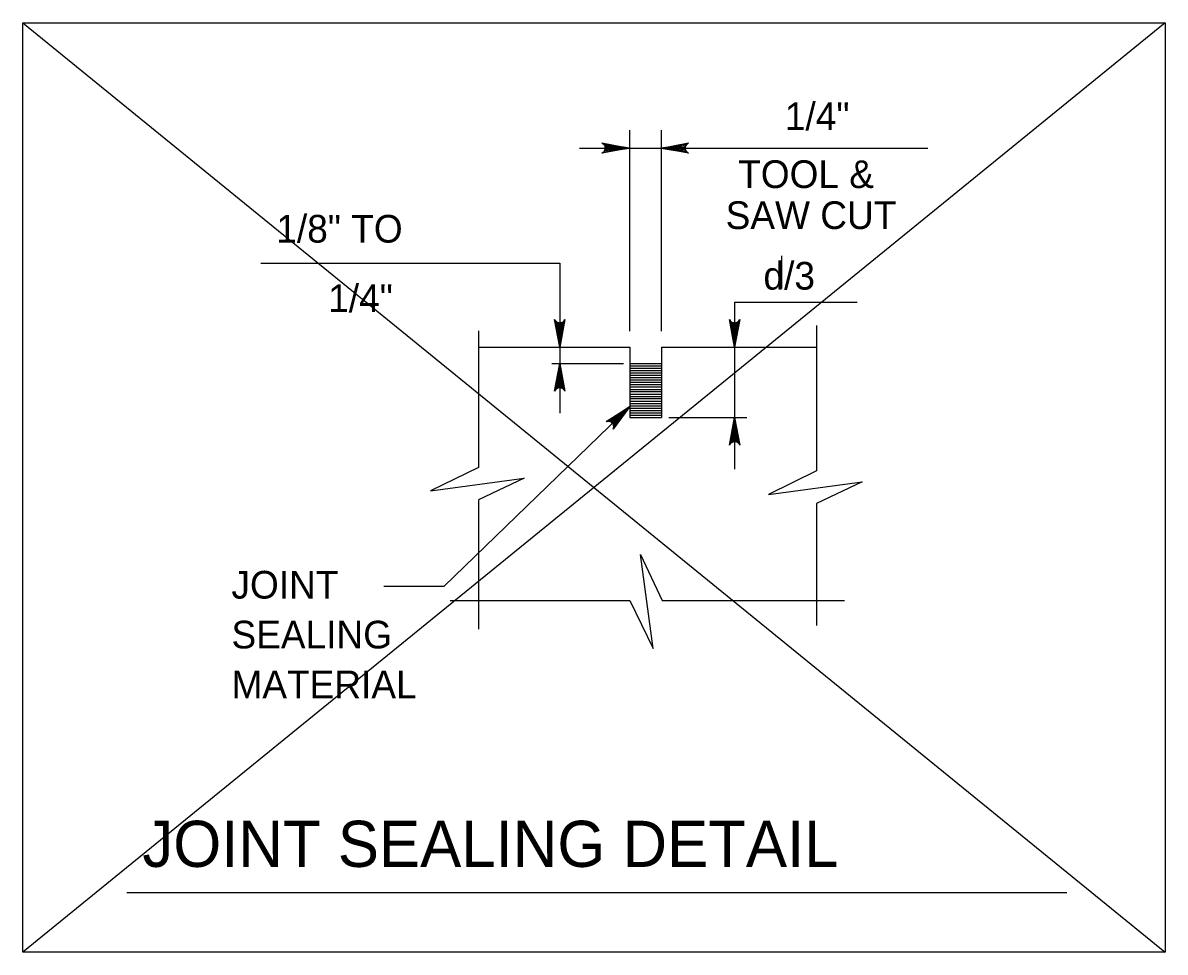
# Model space of a CAD drawing. Extents: x 638079 to 640019, y 297691 to 298879.
# Drawn here: x 638078.5 to 638202.3, y 298460 to 298560.7 of the extents above; entities that cross this region are included whole.
import ezdxf

# ---------------------------------------------------------------- set-up
doc = ezdxf.new("R2010")
doc.units = 0
for name, color, linetype in [('1', 7, 'Continuous'), ('2', 7, 'Continuous'), ('Level 1', 7, 'Continuous')]:
    doc.layers.add(name, color=color, linetype=linetype)

msp = doc.modelspace()

# ---------------------------------------------------------------- linework, layer by layer
at = {"layer": '1'}
for p, q in [((638144.26, 298549.04), (638144.26, 298527.26)), ((638147.69, 298549.04), (638147.69, 298527.26)), ((638138.83, 298547.09), (638176.59, 298547.09)), ((638104.31, 298534.63), (638136.71, 298534.63)), ((638136.71, 298534.63), (638136.71, 298518.38)), ((638160.77, 298531.89), (638160.77, 298535.44)), ((638155.65, 298530.4), (638155.65, 298512.31)), ((638155.65, 298530.4), (638168.92, 298530.4)), ((638127.89, 298527.31), (638127.89, 298512.51)), ((638164.52, 298527.89), (638164.52, 298512.13)), ((638127.89, 298525.54), (638144.31, 298525.54)), ((638144.31, 298525.54), (638144.31, 298517.93)), ((638147.74, 298525.54), (638147.74, 298517.93)), ((638147.74, 298525.54), (638164.52, 298525.54)), ((638135.84, 298523.76), (638143.6, 298523.76)), ((638144.31, 298523.76), (638147.74, 298523.76)), ((638144.31, 298523.51), (638147.74, 298523.51)), ((638144.31, 298523.26), (638147.74, 298523.26)), ((638144.31, 298523), (638147.74, 298523)), ((638144.31, 298522.75), (638147.74, 298522.75)), ((638144.31, 298522.49), (638147.74, 298522.49)), ((638144.31, 298522.24), (638147.74, 298522.24)), ((638144.31, 298521.99), (638147.74, 298521.99)), ((638144.31, 298521.73), (638147.74, 298521.73)), ((638144.31, 298521.48), (638147.74, 298521.48)), ((638144.31, 298521.23), (638147.74, 298521.23)), ((638144.31, 298520.97), (638147.74, 298520.97)), ((638144.31, 298520.72), (638147.74, 298520.72)), ((638144.31, 298520.46), (638147.74, 298520.46)), ((638144.31, 298520.21), (638147.74, 298520.21)), ((638144.31, 298519.96), (638147.74, 298519.96)), ((638144.31, 298519.7), (638147.74, 298519.7)), ((638124.17, 298499.65), (638144.31, 298519.1)), ((638144.31, 298519.45), (638147.74, 298519.45)), ((638144.31, 298519.2), (638147.74, 298519.2)), ((638144.31, 298518.94), (638147.74, 298518.94)), ((638144.31, 298518.69), (638147.74, 298518.69)), ((638144.31, 298518.43), (638147.74, 298518.43)), ((638144.31, 298518.18), (638147.74, 298518.18)), ((638144.31, 298517.93), (638147.74, 298517.93)), ((638148.52, 298517.93), (638156.99, 298517.93)), ((638127.89, 298509), (638127.89, 298495.01)), ((638164.52, 298508.61), (638164.52, 298495.4)), ((638117.64, 298499.65), (638124.17, 298499.65)), ((638124.84, 298498.11), (638144.3, 298498.11)), ((638147.82, 298498.11), (638167.56, 298498.11))]:
    msp.add_line(p, q, dxfattribs=at)
for points in [[(638144.26, 298547.09), (638141.28, 298546.53), (638141.39, 298546.61), (638141.51, 298546.69), (638141.57, 298546.79), (638141.63, 298546.89), (638141.64, 298546.99), (638141.66, 298547.09), (638141.64, 298547.19), (638141.63, 298547.29), (638141.57, 298547.39), (638141.51, 298547.49), (638141.39, 298547.57), (638141.28, 298547.65), (638144.26, 298547.09), (638141.39, 298547.57), (638141.51, 298547.49), (638144.26, 298547.09), (638141.57, 298547.39), (638141.63, 298547.29), (638144.26, 298547.09), (638141.64, 298547.19), (638141.66, 298547.09), (638144.26, 298547.09), (638141.64, 298546.99), (638141.63, 298546.89), (638144.26, 298547.09), (638141.57, 298546.79), (638141.51, 298546.69), (638144.26, 298547.09), (638141.39, 298546.61)], [(638147.69, 298547.09), (638150.67, 298547.65), (638150.56, 298547.57), (638150.44, 298547.49), (638150.38, 298547.39), (638150.32, 298547.29), (638150.31, 298547.19), (638150.29, 298547.09), (638150.31, 298546.99), (638150.32, 298546.89), (638150.38, 298546.79), (638150.44, 298546.69), (638150.56, 298546.61), (638150.67, 298546.53), (638147.69, 298547.09), (638150.56, 298546.61), (638150.44, 298546.69), (638147.69, 298547.09), (638150.38, 298546.79), (638150.32, 298546.89), (638147.69, 298547.09), (638150.31, 298546.99), (638150.29, 298547.09), (638147.69, 298547.09), (638150.31, 298547.19), (638150.32, 298547.29), (638147.69, 298547.09), (638150.38, 298547.39), (638150.44, 298547.49), (638147.69, 298547.09), (638150.56, 298547.57)], [(638136.71, 298525.54), (638136.15, 298528.52), (638136.23, 298528.41), (638136.31, 298528.29), (638136.41, 298528.23), (638136.51, 298528.17), (638136.61, 298528.16), (638136.71, 298528.14), (638136.81, 298528.16), (638136.91, 298528.17), (638137.01, 298528.23), (638137.11, 298528.29), (638137.18, 298528.41), (638137.26, 298528.52), (638136.71, 298525.54), (638137.18, 298528.41), (638137.11, 298528.29), (638136.71, 298525.54), (638137.01, 298528.23), (638136.91, 298528.17), (638136.71, 298525.54), (638136.81, 298528.16), (638136.71, 298528.14), (638136.71, 298525.54), (638136.61, 298528.16), (638136.51, 298528.17), (638136.71, 298525.54), (638136.41, 298528.23), (638136.31, 298528.29), (638136.71, 298525.54), (638136.23, 298528.41)], [(638155.65, 298525.54), (638155.09, 298528.52), (638155.17, 298528.41), (638155.25, 298528.29), (638155.35, 298528.23), (638155.45, 298528.17), (638155.55, 298528.16), (638155.65, 298528.14), (638155.75, 298528.16), (638155.85, 298528.17), (638155.95, 298528.23), (638156.05, 298528.29), (638156.13, 298528.41), (638156.21, 298528.52), (638155.65, 298525.54), (638156.13, 298528.41), (638156.05, 298528.29), (638155.65, 298525.54), (638155.95, 298528.23), (638155.85, 298528.17), (638155.65, 298525.54), (638155.75, 298528.16), (638155.65, 298528.14), (638155.65, 298525.54), (638155.55, 298528.16), (638155.45, 298528.17), (638155.65, 298525.54), (638155.35, 298528.23), (638155.25, 298528.29), (638155.65, 298525.54), (638155.17, 298528.41)], [(638136.71, 298523.76), (638137.26, 298520.78), (638137.18, 298520.9), (638137.11, 298521.01), (638137.01, 298521.07), (638136.91, 298521.13), (638136.81, 298521.15), (638136.71, 298521.16), (638136.61, 298521.15), (638136.51, 298521.13), (638136.41, 298521.07), (638136.31, 298521.01), (638136.23, 298520.9), (638136.15, 298520.78), (638136.71, 298523.76), (638136.23, 298520.9), (638136.31, 298521.01), (638136.71, 298523.76), (638136.41, 298521.07), (638136.51, 298521.13), (638136.71, 298523.76), (638136.61, 298521.15), (638136.71, 298521.16), (638136.71, 298523.76), (638136.81, 298521.15), (638136.91, 298521.13), (638136.71, 298523.76), (638137.01, 298521.07), (638137.11, 298521.01), (638136.71, 298523.76), (638137.18, 298520.9)], [(638144.31, 298519.1), (638142.51, 298516.66), (638142.54, 298516.79), (638142.57, 298516.93), (638142.54, 298517.04), (638142.52, 298517.16), (638142.46, 298517.24), (638142.41, 298517.33), (638142.33, 298517.39), (638142.25, 298517.45), (638142.13, 298517.48), (638142.02, 298517.52), (638141.88, 298517.5), (638141.75, 298517.48), (638144.31, 298519.1), (638141.88, 298517.5), (638142.02, 298517.52), (638144.31, 298519.1), (638142.13, 298517.48), (638142.25, 298517.45), (638144.31, 298519.1), (638142.33, 298517.39), (638142.41, 298517.33), (638144.31, 298519.1), (638142.46, 298517.24), (638142.52, 298517.16), (638144.31, 298519.1), (638142.54, 298517.04), (638142.57, 298516.93), (638144.31, 298519.1), (638142.54, 298516.79)], [(638155.65, 298517.93), (638156.21, 298514.94), (638156.13, 298515.06), (638156.05, 298515.17), (638155.95, 298515.23), (638155.85, 298515.29), (638155.75, 298515.31), (638155.65, 298515.33), (638155.55, 298515.31), (638155.45, 298515.29), (638155.35, 298515.23), (638155.25, 298515.17), (638155.17, 298515.06), (638155.09, 298514.94), (638155.65, 298517.93), (638155.17, 298515.06), (638155.25, 298515.17), (638155.65, 298517.93), (638155.35, 298515.23), (638155.45, 298515.29), (638155.65, 298517.93), (638155.55, 298515.31), (638155.65, 298515.33), (638155.65, 298517.93), (638155.75, 298515.31), (638155.85, 298515.29), (638155.65, 298517.93), (638155.95, 298515.23), (638156.05, 298515.17), (638155.65, 298517.93), (638156.13, 298515.06)], [(638127.89, 298512.51), (638122.71, 298509.98), (638132.85, 298511.36), (638127.89, 298509)], [(638164.52, 298512.13), (638159.34, 298509.59), (638169.49, 298510.97), (638164.52, 298508.61)], [(638144.3, 298498.11), (638146.84, 298492.92), (638145.46, 298503.07), (638147.82, 298498.11)]]:
    msp.add_lwpolyline(points, dxfattribs=at)
at = {"layer": '2'}
for p, q in [((638078.54, 298560.66), (638202.3, 298460.02)), ((638202.3, 298560.66), (638078.54, 298460.02))]:
    msp.add_line(p, q, dxfattribs=at)
msp.add_lwpolyline([(638078.54, 298560.66), (638202.3, 298560.66), (638202.3, 298460.02), (638078.54, 298460.02)], close=True, dxfattribs=at)
at = {"layer": 'Level 1'}
msp.add_line((638089.82, 298466.48), (638191.63, 298466.48), dxfattribs=at)

# ---------------------------------------------------------------- texts
at = {"layer": '1'}
for s, height, p in [('1/4"', 3, (638161.1, 298549.04)), ('TOOL &', 3, (638156.04, 298542.77)), ('SAW CUT', 3, (638154.68, 298538.33)), ('1/8" TO', 3, (638106, 298536.86)), ('d/3', 3, (638158.78, 298531.77)), ('1/4"', 3, (638111.62, 298529.33)), ('JOINT', 3, (638101.14, 298498.31)), ('SEALING', 3, (638101.14, 298492.91)), ('MATERIAL', 3, (638101.14, 298487.51)), ('JOINT SEALING DETAIL', 5, (638091.49, 298469.25))]:
    msp.add_text(s, height=height, dxfattribs=at).set_placement(p)

doc.saveas('drawing.dxf')
